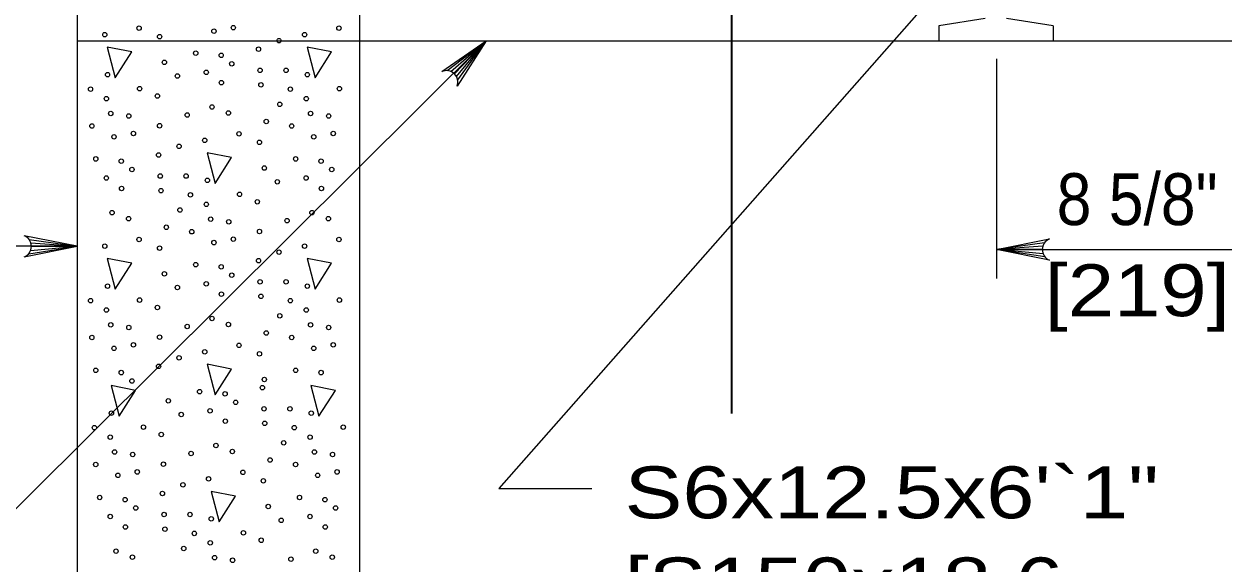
# Model space of a CAD drawing. Extents: x 1352.5 to 1386.5, y 735.9 to 779.9.
# Drawn here: x 1375.419 to 1379.027, y 772.96 to 774.581 of the extents above; entities that cross this region are included whole.
import ezdxf
from ezdxf.enums import TextEntityAlignment as Align

# ---------------------------------------------------------------- set-up
doc = ezdxf.new("R2010")
doc.units = 0
doc.header["$LTSCALE"] = 0.062
doc.layers.add('1', color=7, linetype='Continuous', lineweight=13)

msp = doc.modelspace()

# ---------------------------------------------------------------- linework, layer by layer
at = {"layer": '1', "lineweight": 35}
msp.add_line((1377.54633, 773.4095), (1377.54633, 776.94783), dxfattribs=at)
at = {"layer": '1'}
for p, q in [((1378.30892, 774.59767), (1378.16892, 774.57517)), ((1378.16892, 774.57517), (1378.16892, 774.53017)), ((1378.51258, 774.57517), (1378.37258, 774.59767)), ((1378.51258, 774.57517), (1378.51258, 774.53017)), ((1376.69092, 774.4405), (1376.80792, 774.53058)), ((1376.7015, 774.43808), (1376.80792, 774.53058)), ((1376.71258, 774.43092), (1376.80792, 774.53058)), ((1376.71892, 774.42283), (1376.80792, 774.53058)), ((1376.72275, 774.41242), (1376.80792, 774.53058)), ((1378.34242, 774.47642), (1378.34242, 773.81492)), ((1375.43442, 773.93233), (1375.57867, 773.91217)), ((1375.57867, 773.91217), (1374.33825, 773.91217)), ((1375.43275, 773.88983), (1375.57867, 773.91217)), ((1375.43825, 773.89917), (1375.57867, 773.91217)), ((1375.43933, 773.92233), (1375.57867, 773.91217)), ((1375.44075, 773.91217), (1375.57867, 773.91217)), ((1378.48667, 773.92258), (1378.34242, 773.90242)), ((1378.48175, 773.91267), (1378.34242, 773.90242)), ((1378.34242, 773.90242), (1379.23192, 773.90242)), ((1378.48033, 773.90242), (1378.34242, 773.90242)), ((1378.48283, 773.8895), (1378.34242, 773.90242)), ((1378.48833, 773.88017), (1378.34242, 773.90242))]:
    msp.add_line(p, q, dxfattribs=at)
at = {"layer": '1', "lineweight": 25}
msp.add_line((1375.57867, 774.53017), (1380.0815, 774.53017), dxfattribs=at)
for points in [[(1376.42825, 772.01167), (1376.42825, 775.06992), (1376.34325, 775.15983)], [(1375.57867, 774.88233), (1375.57867, 772.89383), (1375.57867, 770.66242)]]:
    msp.add_lwpolyline(points, dxfattribs=at)
at = {"layer": '1'}
for points in [[(1378.29625, 774.83042), (1376.84667, 773.18408), (1377.12583, 773.18408)], [(1376.80792, 774.53058), (1375.03217, 772.76333), (1376.67692, 771.33608)], [(1376.67475, 774.4375), (1376.80792, 774.53058), (1376.72083, 774.39342)], [(1375.41933, 773.88025), (1375.57867, 773.91217), (1375.41933, 773.944)], [(1378.50175, 773.87058), (1378.34242, 773.90242), (1378.50175, 773.93433)]]:
    msp.add_lwpolyline(points, dxfattribs=at)
for points in [[(1375.66892, 774.51142), (1375.69317, 774.41917), (1375.74267, 774.497)], [(1376.26967, 774.51142), (1376.29392, 774.41917), (1376.34342, 774.497)], [(1375.96933, 774.19333), (1375.99358, 774.10117), (1376.043, 774.17892)], [(1375.66892, 773.87533), (1375.69317, 773.78317), (1375.74267, 773.861)], [(1376.26967, 773.87533), (1376.29392, 773.78317), (1376.34342, 773.861)], [(1375.96933, 773.55733), (1375.99358, 773.46517), (1376.043, 773.54292)], [(1375.6805, 773.49325), (1375.70483, 773.40108), (1375.75433, 773.47883)], [(1376.28125, 773.49325), (1376.30558, 773.40108), (1376.355, 773.47883)], [(1375.98092, 773.17517), (1376.00525, 773.083), (1376.05467, 773.16083)]]:
    msp.add_lwpolyline(points, close=True, dxfattribs=at)
for centre, start, end in [((1376.6889, 774.40612), 338.36113, 114.18726), ((1375.40646, 773.91218), 292.08605, 67.91218), ((1378.51461, 773.90247), 112.08782, 247.91395)]:
    msp.add_arc(centre, 0.03438, start, end, dxfattribs=at)
for centre in [(1375.76462, 774.56855), (1376.04798, 774.56972), (1376.36538, 774.56855), (1375.66164, 774.54878), (1375.8263, 774.54279), (1375.98955, 774.55938), (1376.2624, 774.54878), (1376.12372, 774.505), (1376.1853, 774.53076), (1375.84092, 774.46552), (1375.93498, 774.49302), (1376.01153, 774.4864), (1376.04342, 774.46122), (1375.66975, 774.42857), (1375.87986, 774.42428), (1375.96662, 774.43546), (1376.12858, 774.44145), (1376.20648, 774.44145), (1376.27051, 774.42857), (1376.01233, 774.40424), (1376.13098, 774.39767), (1375.61868, 774.38479), (1375.6665, 774.35644), (1375.76627, 774.38649), (1375.81979, 774.36417), (1376.21944, 774.38479), (1376.26725, 774.35644), (1376.36703, 774.38649), (1375.98395, 774.33126), (1376.18775, 774.33926), (1375.67951, 774.31181), (1375.73383, 774.30402), (1375.9093, 774.30725), (1376.03341, 774.31324), (1376.14695, 774.28748), (1376.28027, 774.31181), (1376.33459, 774.30402), (1375.62269, 774.27402), (1375.7476, 774.2517), (1375.8263, 774.27481), (1376.065, 774.25054), (1376.22345, 774.27402), (1376.34836, 774.2517), (1375.68917, 774.24137), (1375.88492, 774.21275), (1375.96202, 774.23077), (1376.12668, 774.22478), (1376.28993, 774.24137), (1375.6346, 774.17501), (1375.82334, 774.18699), (1376.23536, 774.17501), (1375.71115, 774.16838), (1375.74304, 774.14321), (1376.14129, 774.1475), (1376.31191, 774.16838), (1376.3438, 774.14321), (1375.66624, 774.11745), (1375.8282, 774.12344), (1375.9061, 774.12344), (1375.97013, 774.11056), (1376.18024, 774.10626), (1376.267, 774.11745), (1375.71195, 774.08623), (1375.8306, 774.07966), (1375.91906, 774.06678), (1376.06665, 774.06847), (1376.31271, 774.08623), (1375.96687, 774.03842), (1376.12017, 774.04616), (1375.68357, 774.01325), (1375.73303, 773.99522), (1375.88737, 774.02125), (1375.97989, 773.99379), (1376.28432, 774.01325), (1376.33379, 773.99522), (1375.84657, 773.96947), (1375.92307, 773.956), (1376.03421, 773.986), (1376.12668, 773.9568), (1376.20968, 773.98924), (1375.76462, 773.93252), (1375.98955, 773.92335), (1376.04798, 773.93369), (1376.36538, 773.93252), (1375.66164, 773.91275), (1375.8263, 773.90676), (1376.1853, 773.89473), (1376.2624, 773.91275), (1375.93498, 773.85699), (1376.01153, 773.85037), (1376.12372, 773.86897), (1375.84092, 773.82949), (1376.04342, 773.82519), (1375.66975, 773.79254), (1375.87986, 773.78825), (1375.96662, 773.79943), (1376.12858, 773.80542), (1376.20648, 773.80542), (1376.27051, 773.79254), (1375.61868, 773.74876), (1375.76627, 773.75046), (1376.01233, 773.76822), (1376.13098, 773.76164), (1376.21944, 773.74876), (1376.36703, 773.75046), (1375.6665, 773.72041), (1375.81979, 773.72815), (1376.18775, 773.70323), (1376.26725, 773.72041), (1375.67951, 773.67578), (1375.73383, 773.66799), (1375.9093, 773.67122), (1375.98395, 773.69523), (1376.03341, 773.67721), (1376.28027, 773.67578), (1376.33459, 773.66799), (1375.62269, 773.63799), (1375.8263, 773.63878), (1376.14695, 773.65145), (1376.22345, 773.63799), (1375.68917, 773.60534), (1375.7476, 773.61567), (1375.96202, 773.59474), (1376.065, 773.61451), (1376.28993, 773.60534), (1376.34836, 773.61567), (1375.88492, 773.57672), (1376.12668, 773.58875), (1375.6346, 773.53898), (1375.71115, 773.53235), (1375.82334, 773.55096), (1376.23536, 773.53898), (1376.31191, 773.53235), (1375.74304, 773.50718), (1376.13535, 773.48686), (1376.14129, 773.51147), (1375.94661, 773.47488), (1376.02316, 773.46826), (1375.85255, 773.44737), (1375.97825, 773.41732), (1376.05505, 773.44308), (1376.14021, 773.42331), (1376.21811, 773.42331), (1375.68138, 773.41043), (1375.8915, 773.40614), (1376.02396, 773.3861), (1376.14261, 773.37953), (1376.28214, 773.41043), (1375.63032, 773.36665), (1375.7779, 773.36835), (1375.83142, 773.34603), (1376.23107, 773.36665), (1376.37866, 773.36835), (1375.67813, 773.33829), (1375.99558, 773.31312), (1376.19938, 773.32112), (1376.27888, 773.33829), (1375.69114, 773.29367), (1375.74546, 773.28587), (1375.92093, 773.28911), (1376.04504, 773.2951), (1376.15858, 773.26934), (1376.2919, 773.29367), (1376.34622, 773.28587), (1375.63432, 773.25587), (1375.75923, 773.23356), (1375.83793, 773.25667), (1376.23508, 773.25587), (1376.35999, 773.23356), (1375.7008, 773.22322), (1375.97365, 773.21262), (1376.07663, 773.23239), (1376.13831, 773.20664), (1376.30156, 773.22322), (1375.83497, 773.16884), (1375.89655, 773.1946), (1375.64624, 773.15687), (1375.72278, 773.15024), (1375.75467, 773.12506), (1376.15292, 773.12936), (1376.24699, 773.15687), (1376.32354, 773.15024), (1376.35543, 773.12506), (1375.67788, 773.0993), (1375.83983, 773.10529), (1375.91773, 773.10529), (1375.98176, 773.09241), (1376.27863, 773.0993), (1375.72358, 773.06809), (1375.84223, 773.06151), (1376.19187, 773.08812), (1376.32434, 773.06809), (1375.93069, 773.04863), (1375.9785, 773.02028), (1376.07828, 773.05033), (1376.1318, 773.02802), (1375.6952, 772.9951), (1375.899, 773.00311), (1376.29596, 772.9951), (1375.74466, 772.97708), (1375.99152, 772.97565), (1376.04584, 772.96786), (1376.22131, 772.97109), (1376.34542, 772.97708)]:
    msp.add_ellipse(centre, major_axis=(0, 0.0068), ratio=0.944544, dxfattribs=at)

# ---------------------------------------------------------------- texts
for s, width, p in [('8 5/8"', 0.9, (1378.76562, 773.976)), ('[219]', 1.2, (1378.76562, 773.702))]:
    msp.add_text(s, height=0.156, dxfattribs=dict(at, width=width)).set_placement(p, align=Align.CENTER)
at = {"layer": '1', "width": 1.25}
for s, p in [('S6x12.5x6\'`1"', (1377.22425, 773.09408)), ('[S150x18.6', (1377.22425, 772.82008))]:
    msp.add_text(s, height=0.156, dxfattribs=at).set_placement(p)

doc.saveas('drawing.dxf')
